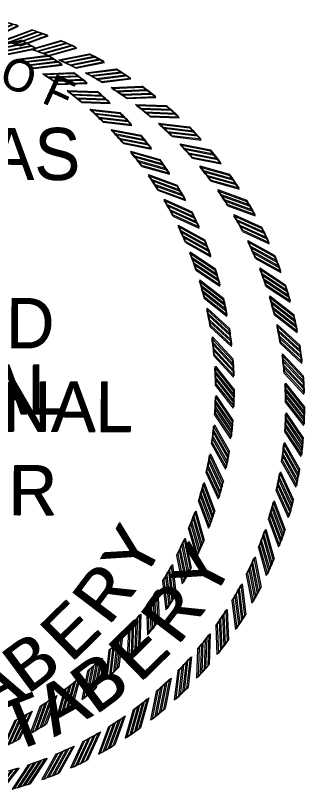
# Model space of a CAD drawing. Extents: x 1373884 to 1377798, y 1168424 to 1170626.
# Drawn here: x 1376888.6 to 1376977.2, y 1168434.3 to 1168673.1 of the extents above; entities that cross this region are included whole.
import ezdxf

# ---------------------------------------------------------------- set-up
doc = ezdxf.new("R2010")
doc.units = 0
for name, color, linetype in [('Default', 7, 'Continuous'), ('G-ANNO-SYMB', 7, 'Continuous'), ('G-ANNO-TEXT', 7, 'Continuous')]:
    doc.layers.add(name, color=color, linetype=linetype)

# ---------------------------------------------------------------- blocks, each defined once
blk = doc.blocks.new('RP')
at = {"layer": 'Default'}
for p, q in [((-0.0781, 1.2656), (0.003, 1.33)), ((-0.058, 1.2667), (0.0216, 1.3299)), ((-0.0375, 1.2674), (0.0405, 1.3294)), ((-0.0176, 1.2679), (0.059, 1.3287))]:
    blk.add_line(p, q, dxfattribs=at)
for radius, start, end in [(1.33, 87.4562, 89.8699), (1.268, 90.7933, 93.5307)]:
    blk.add_arc((0, 0), radius, start, end, dxfattribs=at)

msp = doc.modelspace()

# ---------------------------------------------------------------- block references
at = {"layer": 'Default'}
for p, xscale, yscale, rotation in [((1376855.79, 1168553.54), 91.17655343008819, 91.17655343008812, -13.499999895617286), ((1376855.59, 1168553.5), 91.17655343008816, 91.17655343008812, -13.695800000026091), ((1376855.79, 1168553.54), 91.17655343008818, 91.17655343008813, -17.999999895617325), ((1376855.59, 1168553.5), 91.17655343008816, 91.1765534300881, -18.195800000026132), ((1376855.79, 1168553.54), 91.17655343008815, 91.17655343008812, -22.499999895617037), ((1376855.59, 1168553.5), 91.17655343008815, 91.17655343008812, -22.695800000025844), ((1376855.79, 1168553.54), 91.17655343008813, 91.17655343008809, -26.999999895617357), ((1376855.59, 1168553.5), 91.17655343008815, 91.1765534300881, -27.19580000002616), ((1376855.79, 1168553.54), 91.17655343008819, 91.17655343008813, -31.49999989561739), ((1376855.59, 1168553.5), 91.17655343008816, 91.17655343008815, -31.695800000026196), ((1376855.79, 1168553.54), 91.17655343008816, 91.17655343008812, -35.99999989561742), ((1376855.59, 1168553.5), 91.17655343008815, 91.17655343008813, -36.195800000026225), ((1376855.79, 1168553.54), 91.17655343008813, 91.17655343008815, -40.49999989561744), ((1376855.59, 1168553.5), 91.17655343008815, 91.17655343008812, -40.69580000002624), ((1376855.79, 1168553.54), 91.17655343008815, 91.17655343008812, -44.99999989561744), ((1376855.59, 1168553.5), 91.17655343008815, 91.17655343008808, -45.19580000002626), ((1376855.79, 1168553.54), 91.1765534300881, 91.1765534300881, -49.499999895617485), ((1376855.59, 1168553.5), 91.1765534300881, 91.1765534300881, -49.695800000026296), ((1376855.79, 1168553.54), 91.17655343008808, 91.17655343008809, -53.999999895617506), ((1376855.59, 1168553.5), 91.17655343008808, 91.17655343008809, -54.1958000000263), ((1376855.79, 1168553.54), 91.1765534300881, 91.17655343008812, -58.49999989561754), ((1376855.59, 1168553.5), 91.1765534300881, 91.1765534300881, -58.695800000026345), ((1376855.79, 1168553.54), 91.17655343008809, 91.17655343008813, -62.999999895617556), ((1376855.59, 1168553.5), 91.17655343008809, 91.17655343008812, -63.19580000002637), ((1376855.59, 1168553.5), 91.1765534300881, 91.17655343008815, -67.69580000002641), ((1376855.79, 1168553.54), 91.1765534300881, 91.17655343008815, -67.49999989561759), ((1376855.59, 1168553.5), 91.1765534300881, 91.17655343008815, -72.19580000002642), ((1376855.79, 1168553.54), 91.1765534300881, 91.17655343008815, -71.99999989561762), ((1376855.59, 1168553.5), 91.17655343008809, 91.17655343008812, -76.69580000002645), ((1376855.79, 1168553.54), 91.17655343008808, 91.1765534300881, -76.49999989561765), ((1376855.59, 1168553.5), 91.17655343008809, 91.17655343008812, -81.19580000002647), ((1376855.79, 1168553.54), 91.17655343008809, 91.17655343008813, -80.99999989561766), ((1376855.59, 1168553.5), 91.17655343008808, 91.17655343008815, -85.69580000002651), ((1376855.79, 1168553.54), 91.1765534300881, 91.17655343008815, -85.49999989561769), ((1376855.79, 1168553.54), 91.1765534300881, 91.17655343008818, -89.99999989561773), ((1376855.59, 1168553.5), 91.17655343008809, 91.17655343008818, -90.19580000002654), ((1376855.59, 1168553.5), 91.1765534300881, 91.17655343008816, -94.69580000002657), ((1376855.79, 1168553.54), 91.17655343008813, 91.17655343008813, -94.49999989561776), ((1376855.59, 1168553.5), 91.1765534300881, 91.17655343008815, -99.19580000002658), ((1376855.79, 1168553.54), 91.17655343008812, 91.17655343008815, -98.99999989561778), ((1376855.59, 1168553.5), 91.17655343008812, 91.17655343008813, -103.69580000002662), ((1376855.79, 1168553.54), 91.1765534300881, 91.17655343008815, -103.49999989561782), ((1376855.59, 1168553.5), 91.1765534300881, 91.17655343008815, -108.19580000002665), ((1376855.79, 1168553.54), 91.17655343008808, 91.17655343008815, -107.99999989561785), ((1376855.59, 1168553.5), 91.1765534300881, 91.17655343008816, -112.69580000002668), ((1376855.79, 1168553.54), 91.1765534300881, 91.17655343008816, -112.49999989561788), ((1376855.59, 1168553.5), 91.17655343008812, 91.17655343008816, -117.19580000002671), ((1376855.79, 1168553.54), 91.17655343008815, 91.17655343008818, -116.9999998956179), ((1376855.59, 1168553.5), 91.17655343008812, 91.17655343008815, -121.69580000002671), ((1376855.79, 1168553.54), 91.17655343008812, 91.17655343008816, -121.4999998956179), ((1376855.79, 1168553.54), 91.17655343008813, 91.17655343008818, -125.99999989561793), ((1376855.59, 1168553.5), 91.17655343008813, 91.17655343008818, -126.19580000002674), ((1376855.59, 1168553.5), 91.1765534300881, 91.17655343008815, -130.6958000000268), ((1376855.79, 1168553.54), 91.17655343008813, 91.17655343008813, -130.49999989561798), ((1376855.59, 1168553.5), 91.17655343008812, 91.17655343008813, -135.19580000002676), ((1376855.79, 1168553.54), 91.17655343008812, 91.17655343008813, -134.99999989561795), ((1376855.59, 1168553.5), 91.1765534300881, 91.17655343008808, -139.69580000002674), ((1376855.79, 1168553.54), 91.17655343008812, 91.17655343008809, -139.49999989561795), ((1376855.59, 1168553.5), 91.17655343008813, 91.17655343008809, -144.19580000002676), ((1376855.79, 1168553.54), 91.17655343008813, 91.17655343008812, -143.99999989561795), ((1376855.59, 1168553.5), 91.17655343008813, 91.17655343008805, -148.69580000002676), ((1376855.79, 1168553.54), 91.17655343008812, 91.17655343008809, -148.49999989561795), ((1376855.59, 1168553.5), 91.17655343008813, 91.17655343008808, -153.1958000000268), ((1376855.79, 1168553.54), 91.17655343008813, 91.17655343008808, -152.99999989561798), ((1376855.59, 1168553.5), 91.17655343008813, 91.17655343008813, -157.6958000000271), ((1376855.79, 1168553.54), 91.17655343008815, 91.17655343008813, -157.4999998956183), ((1376855.79, 1168553.54), 91.17655343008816, 91.1765534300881, -161.99999989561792), ((1376855.59, 1168553.5), 91.17655343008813, 91.17655343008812, -162.19580000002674), ((1376855.59, 1168553.5), 91.17655343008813, 91.17655343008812, -166.69580000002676), ((1376855.79, 1168553.54), 91.17655343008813, 91.17655343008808, -166.49999989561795)]:
    msp.add_blockref('RP', p, dxfattribs=dict(at, xscale=xscale, yscale=yscale, rotation=rotation))
at = {"layer": 'G-ANNO-SYMB'}
for p, xscale, yscale, rotation in [((1376835.56, 1168558.82), 90.20715837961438, 90.20715837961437, -26.999999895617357), ((1376835.36, 1168558.79), 90.2071583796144, 90.20715837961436, -27.19580000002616), ((1376835.56, 1168558.82), 90.20715837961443, 90.2071583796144, -31.49999989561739), ((1376835.36, 1168558.79), 90.20715837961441, 90.2071583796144, -31.695800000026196), ((1376835.56, 1168558.82), 90.20715837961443, 90.20715837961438, -35.999999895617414), ((1376835.36, 1168558.79), 90.2071583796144, 90.20715837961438, -36.195800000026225), ((1376835.56, 1168558.82), 90.2071583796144, 90.2071583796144, -40.49999989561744), ((1376835.36, 1168558.79), 90.2071583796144, 90.20715837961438, -40.69580000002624), ((1376835.56, 1168558.82), 90.2071583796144, 90.20715837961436, -44.99999989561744), ((1376835.36, 1168558.79), 90.20715837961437, 90.20715837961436, -45.19580000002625), ((1376835.56, 1168558.82), 90.20715837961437, 90.20715837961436, -49.499999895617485), ((1376835.36, 1168558.79), 90.20715837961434, 90.20715837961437, -49.695800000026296), ((1376835.56, 1168558.82), 90.20715837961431, 90.20715837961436, -53.999999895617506), ((1376835.36, 1168558.79), 90.20715837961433, 90.20715837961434, -54.1958000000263), ((1376835.56, 1168558.82), 90.20715837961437, 90.20715837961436, -58.49999989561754), ((1376835.36, 1168558.79), 90.20715837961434, 90.20715837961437, -58.695800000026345), ((1376835.36, 1168558.79), 90.20715837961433, 90.20715837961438, -63.19580000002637), ((1376835.56, 1168558.82), 90.20715837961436, 90.20715837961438, -62.99999989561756), ((1376835.36, 1168558.79), 90.20715837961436, 90.20715837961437, -67.69580000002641), ((1376835.56, 1168558.82), 90.20715837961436, 90.2071583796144, -67.49999989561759), ((1376835.36, 1168558.79), 90.20715837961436, 90.2071583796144, -72.19580000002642), ((1376835.56, 1168558.82), 90.20715837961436, 90.2071583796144, -71.99999989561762), ((1376835.36, 1168558.79), 90.20715837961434, 90.20715837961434, -76.69580000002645), ((1376835.56, 1168558.82), 90.20715837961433, 90.20715837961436, -76.49999989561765), ((1376835.56, 1168558.82), 90.20715837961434, 90.2071583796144, -80.99999989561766), ((1376835.36, 1168558.79), 90.20715837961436, 90.2071583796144, -81.19580000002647), ((1376835.56, 1168558.82), 90.20715837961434, 90.20715837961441, -85.49999989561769), ((1376835.36, 1168558.79), 90.20715837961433, 90.20715837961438, -85.69580000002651), ((1376835.36, 1168558.79), 90.20715837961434, 90.20715837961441, -90.19580000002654), ((1376835.56, 1168558.82), 90.20715837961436, 90.20715837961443, -89.99999989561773), ((1376835.36, 1168558.79), 90.20715837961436, 90.20715837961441, -94.69580000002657), ((1376835.56, 1168558.82), 90.20715837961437, 90.20715837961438, -94.49999989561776), ((1376835.36, 1168558.79), 90.20715837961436, 90.2071583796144, -99.19580000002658), ((1376835.56, 1168558.82), 90.20715837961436, 90.2071583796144, -98.99999989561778), ((1376835.36, 1168558.79), 90.20715837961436, 90.2071583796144, -103.69580000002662), ((1376835.56, 1168558.82), 90.20715837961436, 90.20715837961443, -103.49999989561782), ((1376835.36, 1168558.79), 90.20715837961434, 90.2071583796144, -108.19580000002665), ((1376835.56, 1168558.82), 90.20715837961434, 90.2071583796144, -107.99999989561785), ((1376835.36, 1168558.79), 90.20715837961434, 90.20715837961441, -112.69580000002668), ((1376835.56, 1168558.82), 90.20715837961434, 90.20715837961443, -112.49999989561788), ((1376835.36, 1168558.79), 90.20715837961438, 90.20715837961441, -117.19580000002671), ((1376835.56, 1168558.82), 90.2071583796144, 90.20715837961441, -116.9999998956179), ((1376835.36, 1168558.79), 90.20715837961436, 90.20715837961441, -121.69580000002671), ((1376835.56, 1168558.82), 90.20715837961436, 90.20715837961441, -121.4999998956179), ((1376835.36, 1168558.79), 90.20715837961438, 90.2071583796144, -126.19580000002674), ((1376835.56, 1168558.82), 90.20715837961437, 90.20715837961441, -125.99999989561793), ((1376835.36, 1168558.79), 90.20715837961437, 90.20715837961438, -130.6958000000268), ((1376835.56, 1168558.82), 90.20715837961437, 90.20715837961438, -130.49999989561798), ((1376835.36, 1168558.79), 90.20715837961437, 90.20715837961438, -135.19580000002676), ((1376835.56, 1168558.82), 90.20715837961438, 90.20715837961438, -134.99999989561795), ((1376835.36, 1168558.79), 90.20715837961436, 90.20715837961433, -139.69580000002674), ((1376835.56, 1168558.82), 90.20715837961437, 90.20715837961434, -139.49999989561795), ((1376835.36, 1168558.79), 90.20715837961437, 90.20715837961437, -144.19580000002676), ((1376835.56, 1168558.82), 90.2071583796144, 90.20715837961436, -143.99999989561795), ((1376835.56, 1168558.82), 90.20715837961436, 90.20715837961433, -148.49999989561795), ((1376835.36, 1168558.79), 90.20715837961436, 90.20715837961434, -148.69580000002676), ((1376835.36, 1168558.79), 90.20715837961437, 90.20715837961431, -153.1958000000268), ((1376835.56, 1168558.82), 90.20715837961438, 90.20715837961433, -152.99999989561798)]:
    msp.add_blockref('RP', p, dxfattribs=dict(at, xscale=xscale, yscale=yscale, rotation=rotation))

# ---------------------------------------------------------------- texts
at = {"layer": 'Default'}
for s, height, rotation, p in [('O', 9.67, 341.2218, (1376883.18, 1168651.9)), ('O', 9.67, 341.026, (1376883.31, 1168651.77)), ('F', 9.67, 335.3628, (1376896.22, 1168646.8)), ('F', 9.67, 335.167, (1376896.33, 1168646.63)), ('ARKANSAS', 15.788, 0, (1376793.39, 1168622.99)), ('ARKANSAS', 15.788, 359.8042, (1376793.42, 1168623.17)), ('LICENSED', 15.285, 359.8042, (1376798.15, 1168571.62)), ('LICENSED', 15.285, 0, (1376798.29, 1168571.46)), ('PROFESSIONAL', 15.2848, 359.8042, (1376765.31, 1168546.17)), ('PROFESSIONAL', 15.2848, 0, (1376765.54, 1168545.9)), ('ENGINEER', 15.285, 359.8042, (1376794.33, 1168520.51)), ('ENGINEER', 15.285, 0, (1376794.65, 1168520.33)), ('Y', 15.28, 62.5392, (1376948.77, 1168493.52)), ('Y', 15.28, 62.735, (1376949.18, 1168493.87)), ('R', 15.28, 52.9395, (1376938.55, 1168480.37)), ('R', 15.28, 52.7437, (1376938.09, 1168480.06)), ('E', 15.28, 44.306, (1376926.45, 1168468.68)), ('E', 15.28, 44.5018, (1376926.95, 1168468.96)), ('B', 15.28, 36.505, (1376912.96, 1168458.95)), ('B', 15.28, 36.7008, (1376913.49, 1168459.18)), ('A', 15.28, 28.8562, (1376900.27, 1168452.29)), ('A', 15.28, 29.052, (1376900.82, 1168452.47)), ('T', 15.28, 21.4329, (1376887.56, 1168447.5)), ('T', 15.28, 21.6287, (1376888.13, 1168447.65))]:
    msp.add_text(s, height=height, rotation=rotation, dxfattribs=at).set_placement(p)
at = {"layer": 'G-ANNO-TEXT'}
for s, height, rotation, p in [('PROFESSIONAL', 15.1223, 359.8042, (1376746.04, 1168551.53)), ('PROFESSIONAL', 15.1223, 0, (1376746.27, 1168551.26)), ('Y', 15.12, 62.5392, (1376927.55, 1168499.44)), ('Y', 15.12, 62.735, (1376927.95, 1168499.79)), ('R', 15.12, 52.7437, (1376916.99, 1168486.12)), ('R', 15.12, 52.9395, (1376917.44, 1168486.44)), ('E', 15.12, 44.306, (1376905.47, 1168474.87)), ('E', 15.12, 44.5018, (1376905.96, 1168475.14)), ('B', 15.12, 36.505, (1376892.12, 1168465.24)), ('B', 15.12, 36.7008, (1376892.65, 1168465.47)), ('A', 15.12, 28.8562, (1376879.56, 1168458.65)), ('A', 15.12, 29.052, (1376880.11, 1168458.83))]:
    msp.add_text(s, height=height, rotation=rotation, dxfattribs=at).set_placement(p)

doc.saveas('drawing.dxf')
